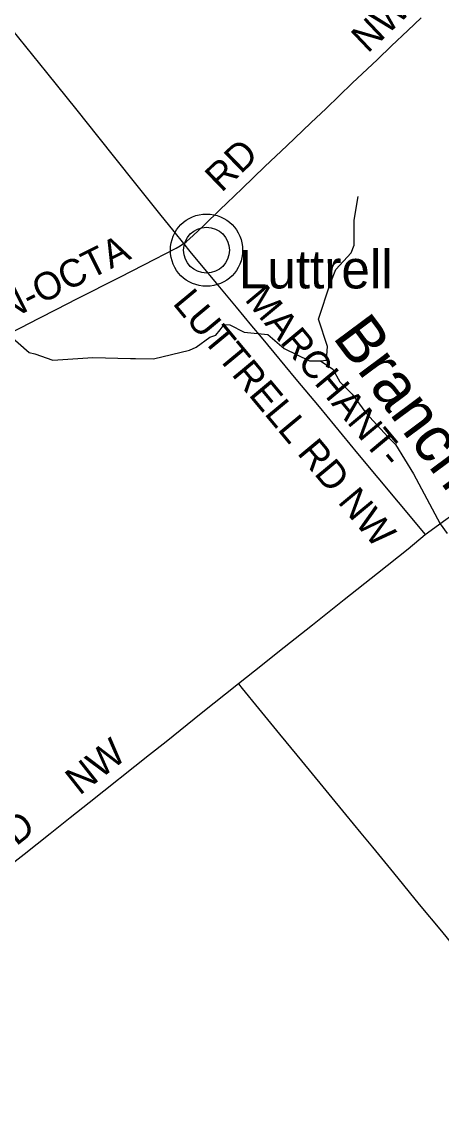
# Model space of a CAD drawing. Extents: x -49 to -8.2, y 9.4 to 23.5.
# Drawn here: x -42.263 to -41.83, y 15.362 to 16.498 of the extents above; entities that cross this region are included whole.
import ezdxf

# ---------------------------------------------------------------- set-up
doc = ezdxf.new("R2010")
doc.units = 0
for name, color, linetype in [('GM_X_County_Road', 7, 'Continuous'), ('GM_X_County_Road_Text', 7, 'Continuous'), ('GM_X_Minor_River', 7, 'Continuous'), ('GM_X_Minor_River_Text', 7, 'Continuous'), ('GM_X_Unincorporated', 7, 'Continuous'), ('GM_X_Unincorporated_Text', 7, 'Continuous')]:
    doc.layers.add(name, color=color, linetype=linetype)

msp = doc.modelspace()

# ---------------------------------------------------------------- linework, layer by layer
at = {"layer": 'GM_X_County_Road'}
for points in [[(-42.4831, 16.7523), (-42.4798, 16.7482), (-42.4724, 16.7391), (-42.4482, 16.7087), (-42.3977, 16.6457), (-42.3734, 16.6154), (-42.3531, 16.5899), (-42.3395, 16.5728), (-42.3299, 16.5609), (-42.3132, 16.5403), (-42.3104, 16.5368), (-42.3048, 16.5298), (-42.2957, 16.5184), (-42.2851, 16.5051), (-42.2734, 16.4905), (-42.2375, 16.4456), (-42.2064, 16.4068), (-42.1851, 16.3802), (-42.1473, 16.3329), (-42.121, 16.3002), (-42.1064, 16.282), (-42.0963, 16.2695)], [(-42.0963, 16.2695), (-42.0959, 16.2697), (-42.0934, 16.2717), (-42.0865, 16.278), (-42.0753, 16.2887), (-42.0585, 16.3048), (-42.0518, 16.3112), (-42.036, 16.3263), (-42.0125, 16.3488), (-41.9901, 16.3703), (-41.9653, 16.3938), (-41.9496, 16.4088), (-41.9226, 16.4346), (-41.8968, 16.4592), (-41.8822, 16.4731), (-41.8653, 16.4891), (-41.8518, 16.502)], [(-42.5476, 16.0408), (-42.5099, 16.0596), (-42.4752, 16.077), (-42.4336, 16.0979), (-42.4004, 16.1148), (-42.3422, 16.1442), (-42.2963, 16.167), (-42.2643, 16.1829), (-42.245, 16.1928), (-42.227, 16.2019), (-42.2063, 16.2126), (-42.162, 16.2351), (-42.1371, 16.2478), (-42.1039, 16.2649), (-42.0998, 16.2672), (-42.0963, 16.2695)], [(-42.0963, 16.2695), (-42.0898, 16.2615), (-42.0611, 16.2267), (-42.0423, 16.204), (-42.0263, 16.1849), (-42.0163, 16.1731), (-42.0035, 16.1575), (-41.9806, 16.1301), (-41.9568, 16.1014), (-41.9171, 16.0536), (-41.8753, 16.0035), (-41.8477, 15.97)], [(-41.8477, 15.97), (-41.8263, 15.9855), (-41.8112, 15.9963), (-41.7849, 16.0152)], [(-42.0398, 15.8167), (-42.0234, 15.8298), (-41.9929, 15.8539), (-41.9637, 15.8771), (-41.9308, 15.9031), (-41.8967, 15.9302), (-41.865, 15.9553), (-41.8477, 15.97)], [(-42.4407, 15.4979), (-42.4127, 15.5201), (-42.3884, 15.5394), (-42.3567, 15.5645), (-42.336, 15.581), (-42.3165, 15.5964), (-42.2982, 15.6109), (-42.2727, 15.6313), (-42.2605, 15.6409), (-42.2338, 15.6623), (-42.213, 15.6786), (-42.1936, 15.6941), (-42.1315, 15.7434), (-42.1144, 15.7569), (-42.0998, 15.7686), (-42.0781, 15.7861), (-42.0398, 15.8167)], [(-41.6676, 15.3621), (-41.6792, 15.3762), (-41.6967, 15.398), (-41.7272, 15.4353), (-41.742, 15.4533), (-41.7656, 15.4822), (-41.7803, 15.5003), (-41.8187, 15.5472), (-41.8305, 15.5616), (-41.8533, 15.5892), (-41.8799, 15.6216), (-41.9015, 15.6481), (-41.9134, 15.6625), (-41.9291, 15.6817), (-41.9666, 15.7274), (-41.9795, 15.7429), (-41.9973, 15.7645), (-42.0189, 15.791), (-42.0357, 15.8114), (-42.0394, 15.8162), (-42.0398, 15.8167)]]:
    msp.add_lwpolyline(points, dxfattribs=at)
at = {"layer": 'GM_X_Minor_River'}
for points in [[(-41.9552, 16.149), (-41.9493, 16.1495), (-41.9482, 16.1635), (-41.9574, 16.1918), (-41.9455, 16.2283), (-41.9394, 16.2429), (-41.9236, 16.2602), (-41.9207, 16.2679), (-41.9206, 16.2938), (-41.9167, 16.318)], [(-42.2752, 16.1749), (-42.2555, 16.1574), (-42.2494, 16.156), (-42.231, 16.1497), (-42.1898, 16.1522), (-42.151, 16.1514), (-42.1459, 16.1512), (-42.1273, 16.1508), (-42.0902, 16.1598), (-42.0833, 16.163), (-42.0693, 16.1731), (-42.063, 16.1753), (-42.0587, 16.1809), (-42.0547, 16.1864), (-42.0486, 16.1858), (-42.0339, 16.1782), (-42.0096, 16.176), (-41.9927, 16.1616), (-41.9666, 16.1487), (-41.9552, 16.149), (-41.9428, 16.1401), (-41.9353, 16.1271), (-41.9226, 16.1146), (-41.9086, 16.0952), (-41.8857, 16.0704), (-41.8782, 16.0628), (-41.8594, 16.0325), (-41.8321, 15.9811), (-41.8248, 15.9711)]]:
    msp.add_lwpolyline(points, dxfattribs=at)
at = {"layer": 'GM_X_Unincorporated'}
for radius in [0.0372, 0.0236]:
    msp.add_circle((-42.0727, 16.2628), radius, dxfattribs=at)

# ---------------------------------------------------------------- texts
at = {"layer": 'GM_X_County_Road_Text'}
for s, height, rotation, p in [('NW', 0.02841, 43.5616, (-41.9067, 16.4648)), ('RD', 0.02841, 44.0414, (-42.0572, 16.3214)), ('PEARSON-OCTA', 0.028409, 26.7655, (-42.4203, 16.1176)), ('MARCHANT-', 0.02841, 309.8193, (-42.0342, 16.2118)), ('LUTTRELL RD NW', 0.028409, 309.7445, (-42.1084, 16.2078)), ('NW', 0.02841, 38.2787, (-42.2035, 15.7008)), ('RD', 0.02841, 38.2345, (-42.2902, 15.6317))]:
    msp.add_text(s, height=height, rotation=rotation, dxfattribs=at).set_placement(p)
at = {"layer": 'GM_X_Minor_River_Text'}
msp.add_text('Branch', height=0.04735, rotation=306.6262, dxfattribs=at).set_placement((-41.9436, 16.1732))
at = {"layer": 'GM_X_Unincorporated_Text'}
msp.add_text('Luttrell', height=0.03949, rotation=0, dxfattribs=at).set_placement((-42.0395, 16.2234))

doc.saveas('drawing.dxf')
